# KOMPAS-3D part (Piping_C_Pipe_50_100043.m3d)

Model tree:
1. Plane XY
2. Plane ZX
3. Plane ZY
4. X Axis
5. Y Axis
6. Z Axis
7. Origin
8. Path  (labels: Труба Dy 50; Отвод 90 Dy 50)
9. Plane of section
10. Section of pipe
11. Pipe
     Толщина стенки 1 = 1

Referenced files in C:\Program Files\ASCON\KOMPAS-3D V10\Libs\Piping\Models\Tanks\: Tanks.a3d
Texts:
  Pipe Dn 50
  Steel ASTM A295
  Three Point Plane
  Plane at Angle
  Line and Point Plane
  Axis through Two Vertices
  Axis of Feature
  Axis of Conical Surface
  Axis through Edge
  Приклеить элемент выдавливания
  Приклеить элемент вращения
  Приклеить кинематический элемент
  Приклеить элемент по сечениям
  Trim by Surface
  Trim by Sketch
  Feature with No History
  Intersection Axis of Two Planes
  Two Line Plane
  Line and Face Plane
  Bend by line
  Hole in sheet body
  Cut in sheet body
  Point in CM
  Linear Dimension from Line to Point
  Surface Finish Symbol
  Geometric Tolerance Symbol
  Текст на чертеже
  Линия-выноска #1
  Линия-выноска #2
  Линия-выноска #3
  Отклонения формы и база
  Марка координационной оси
  Марка/позиционное обозначение с линией-выноской
  Марка/позиционное обозначение на линии
  Марка/позиционное обозначение без линии-выноски
  Труба Dy 50
  Отвод 90 Dy 50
